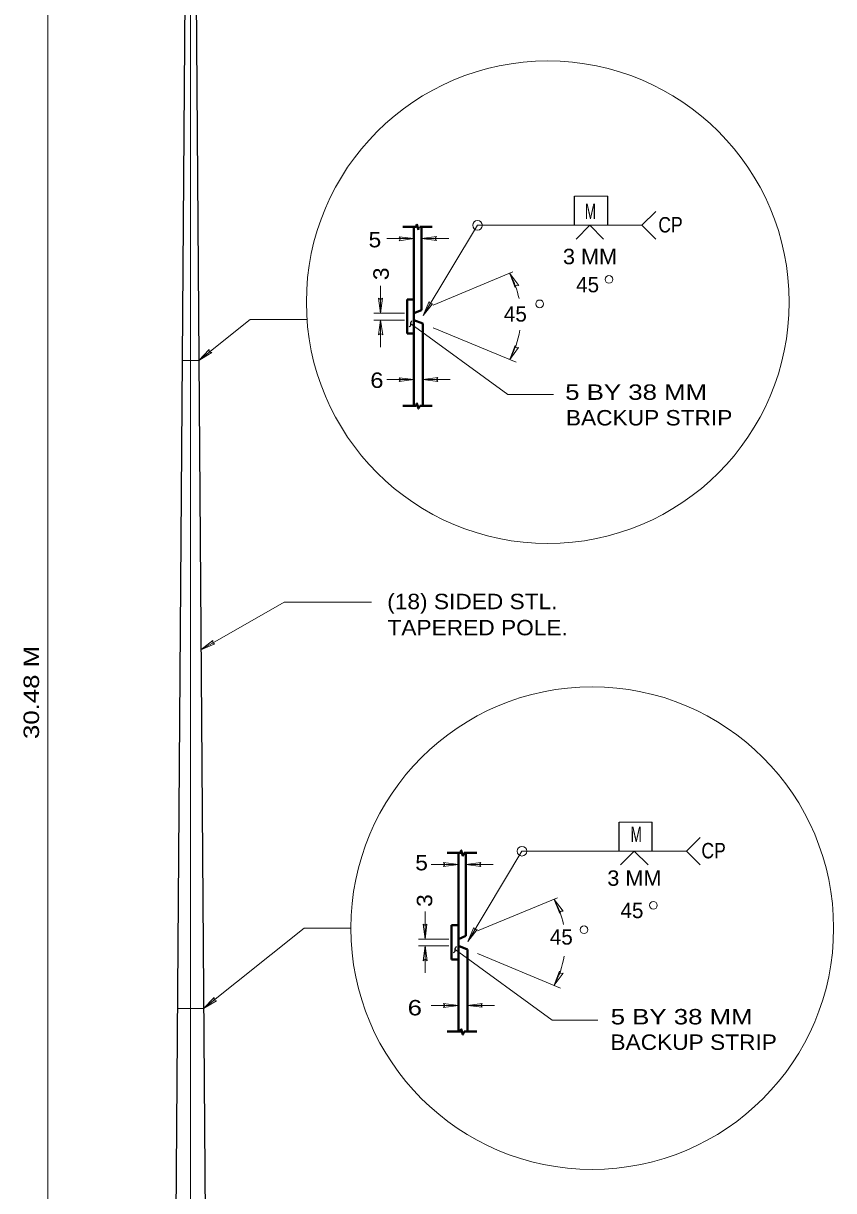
# Model space of a CAD drawing. Extents: x 312583 to 312854, y 144419 to 144597.
# Drawn here: x 312628.1 to 312668, y 144466.1 to 144523.7 of the extents above; entities that cross this region are included whole.
import ezdxf

# ---------------------------------------------------------------- set-up
doc = ezdxf.new("R2010")
doc.units = 0
doc.header["$LTSCALE"] = 0.3
doc.layers.add('1', color=7, linetype='Continuous', lineweight=13)
doc.layers.add('2', color=7, linetype='Continuous', lineweight=13)

msp = doc.modelspace()

# ---------------------------------------------------------------- linework, layer by layer
at = {"layer": '1'}
for p, q in [((312636.3575, 144539.0263), (312636.3575, 144439.0913)), ((312655.2788, 144515.1369), (312656.9118, 144515.1369)), ((312647.5891, 144513.4732), (312647.6504, 144513.6189)), ((312647.3668, 144513.0439), (312646.0251, 144513.0439)), ((312647.7348, 144513.0439), (312649.0764, 144513.0439)), ((312652.2428, 144511.4032), (312648.3098, 144509.7702)), ((312646.9068, 144509.3792), (312645.3888, 144509.3792)), ((312639.2938, 144509.0649), (312636.7714, 144507.0332)), ((312642.0998, 144509.0649), (312639.2938, 144509.0649)), ((312646.9068, 144509.0342), (312645.3888, 144509.0342)), ((312645.7184, 144507.7002), (312645.7184, 144509.0342)), ((312652.3961, 144506.9566), (312648.3098, 144508.6509)), ((312647.3668, 144506.0979), (312646.0251, 144506.0979)), ((312647.8038, 144506.0979), (312649.1531, 144506.0979)), ((312636.8711, 144492.7809), (312640.9651, 144495.1192)), ((312640.9651, 144495.1192), (312645.2661, 144495.1192)), ((312657.4714, 144484.2786), (312659.0968, 144484.2786)), ((312649.5518, 144482.1932), (312648.2101, 144482.1932)), ((312649.9198, 144482.1932), (312651.2614, 144482.1932)), ((312654.4354, 144480.5526), (312650.5024, 144478.9196)), ((312649.0918, 144478.5209), (312647.5814, 144478.5209)), ((312649.0918, 144478.1836), (312647.5814, 144478.1836)), ((312647.9111, 144476.8496), (312647.9111, 144478.1836)), ((312654.5888, 144476.1059), (312650.5024, 144477.8002)), ((312649.5518, 144475.2472), (312648.2101, 144475.2472)), ((312649.9964, 144475.2472), (312651.3381, 144475.2472))]:
    msp.add_line(p, q, dxfattribs=at)
at = {"layer": '1', "lineweight": 25}
for p, q in [((312655.2788, 144513.7032), (312655.2788, 144515.1369)), ((312656.9118, 144513.7032), (312656.9118, 144515.1369)), ((312658.5984, 144513.7032), (312659.2808, 144514.3779)), ((312656.0301, 144513.7032), (312655.3554, 144513.0209)), ((312656.0301, 144513.7032), (312656.7048, 144513.0209)), ((312658.5984, 144513.7032), (312659.2808, 144513.0209)), ((312657.4714, 144482.8526), (312657.4714, 144484.2786)), ((312659.0968, 144482.8526), (312659.0968, 144484.2786)), ((312660.7911, 144482.8526), (312661.4658, 144483.5272)), ((312658.2151, 144482.8526), (312657.5404, 144482.1702)), ((312658.2151, 144482.8526), (312658.8974, 144482.1702)), ((312660.7911, 144482.8526), (312661.4658, 144482.1702))]:
    msp.add_line(p, q, dxfattribs=at)
at = {"layer": '1', "lineweight": 40}
for p, q in [((312647.3668, 144513.6189), (312647.3668, 144509.2106)), ((312648.2638, 144513.6189), (312647.6504, 144513.6189)), ((312647.7348, 144513.6189), (312647.7348, 144509.5249)), ((312647.0294, 144510.0462), (312647.0294, 144508.3672)), ((312647.3668, 144510.0462), (312647.0294, 144510.0462)), ((312647.3668, 144509.3792), (312647.7348, 144509.5249)), ((312647.3668, 144504.8099), (312647.3668, 144509.2106)), ((312647.3668, 144509.0342), (312647.8038, 144508.8579)), ((312647.8038, 144504.8099), (312647.8038, 144508.8579)), ((312647.3668, 144508.3672), (312647.0294, 144508.3672)), ((312648.2638, 144504.8099), (312647.6504, 144504.8099)), ((312649.5518, 144482.7682), (312649.5518, 144478.3599)), ((312650.4564, 144482.7682), (312649.8431, 144482.7682)), ((312649.9198, 144482.7682), (312649.9198, 144478.6742)), ((312649.2144, 144479.1956), (312649.2144, 144477.5166)), ((312649.5518, 144479.1956), (312649.2144, 144479.1956)), ((312649.5518, 144478.5209), (312649.9198, 144478.6742)), ((312649.5518, 144473.9592), (312649.5518, 144478.3599)), ((312649.5518, 144478.1836), (312649.9964, 144477.9996)), ((312649.9964, 144473.9592), (312649.9964, 144477.9996)), ((312649.5518, 144477.5166), (312649.2144, 144477.5166)), ((312650.4564, 144473.9592), (312649.8431, 144473.9592))]:
    msp.add_line(p, q, dxfattribs=at)
for points in [[(312646.8148, 144513.6189), (312647.4664, 144513.6189), (312647.5124, 144513.7416), (312647.5891, 144513.4732)], [(312646.8148, 144504.8099), (312647.4664, 144504.8099), (312647.5124, 144504.9249), (312647.5891, 144504.6642), (312647.6504, 144504.8099)], [(312648.9998, 144482.7682), (312649.6591, 144482.7682), (312649.6974, 144482.8909), (312649.7741, 144482.6226), (312649.8431, 144482.7682)], [(312648.9998, 144473.9592), (312649.6591, 144473.9592), (312649.6974, 144474.0742), (312649.7741, 144473.8136), (312649.8431, 144473.9592)]]:
    msp.add_lwpolyline(points, dxfattribs=at)
at = {"layer": '1'}
for points in [[(312647.8268, 144509.2489), (312650.4948, 144513.7032), (312658.5984, 144513.7032)], [(312646.0634, 144509.3792), (312645.7184, 144509.3792), (312645.7184, 144510.7209)], [(312647.2134, 144508.8502), (312651.9974, 144505.3696), (312654.2361, 144505.3696)], [(312650.0194, 144478.3982), (312652.6874, 144482.8526), (312660.7911, 144482.8526)], [(312648.2484, 144478.5209), (312647.9111, 144478.5209), (312647.9111, 144479.8702)], [(312644.2541, 144479.0576), (312641.9618, 144479.0576), (312637.0014, 144475.0939)], [(312649.3984, 144477.9996), (312654.1824, 144474.5189), (312656.4288, 144474.5189)]]:
    msp.add_lwpolyline(points, dxfattribs=at)
for centre, radius in [((312653.9591, 144509.9109), 11.8926), ((312650.4976, 144513.7016), 0.2381), ((312656.973, 144511.0334), 0.1897), ((312653.5563, 144509.8294), 0.1897), ((312656.148, 144479.06), 11.8926), ((312652.6866, 144482.8506), 0.2381), ((312659.1619, 144480.1824), 0.1897), ((312655.7452, 144478.9784), 0.1897)]:
    msp.add_circle(centre, radius, dxfattribs=at)
for centre, start, end in [((312648.3121, 144509.2089), 11.74697, 29.33835), ((312648.3121, 144509.2089), 330.66165, 350.9999), ((312650.501, 144478.3579), 11.74697, 29.33835), ((312650.501, 144478.3579), 330.66165, 350.9999)]:
    msp.add_arc(centre, 4.3203, start, end, dxfattribs=at)
at = {"layer": '1', "lineweight": 25}
for points in [[(312647.1291, 144508.7046), (312647.1751, 144508.7352), (312647.2058, 144508.7736), (312647.2134, 144508.8272), (312647.2134, 144508.8502), (312647.2134, 144508.8962), (312647.2288, 144508.9346), (312647.2518, 144508.9729), (312647.2671, 144508.9959)], [(312649.3218, 144477.8539), (312649.3678, 144477.8846), (312649.3908, 144477.9229), (312649.3984, 144477.9766), (312649.3984, 144477.9996), (312649.3984, 144478.0456), (312649.4138, 144478.0839), (312649.4368, 144478.1222), (312649.4598, 144478.1452)]]:
    msp.add_spline(points, degree=3, dxfattribs=at)
at = {"layer": '2'}
for p, q in [((312629.3348, 144443.1469), (312629.3348, 144538.9802)), ((312636.7714, 144507.0332), (312635.9434, 144507.0332)), ((312637.0014, 144475.0939), (312635.7058, 144475.0939))]:
    msp.add_line(p, q, dxfattribs=at)
at = {"layer": '2', "lineweight": 25}
for p, q in [((312636.1734, 144538.9802), (312635.4758, 144443.2696)), ((312636.5414, 144538.9802), (312637.2314, 144443.2696))]:
    msp.add_line(p, q, dxfattribs=at)
at = {"layer": '2'}
for points in [[(312646.6308, 144513.1359), (312647.3668, 144513.0439), (312646.6308, 144512.9442), (312646.6998, 144513.0439)], [(312648.4708, 144512.9519), (312647.7348, 144513.0439), (312648.4708, 144513.1512), (312648.3941, 144513.0439)], [(312652.3578, 144510.6366), (312652.0818, 144511.3266), (312652.5264, 144510.7362), (312652.4038, 144510.7439)], [(312645.8104, 144510.1152), (312645.7184, 144509.3792), (312645.6188, 144510.1152), (312645.7184, 144510.0386)], [(312648.2868, 144509.8392), (312647.8268, 144509.2489), (312648.1181, 144509.9389), (312648.1718, 144509.8239)], [(312645.6264, 144508.2982), (312645.7184, 144509.0342), (312645.8258, 144508.2982), (312645.7184, 144508.3749)], [(312652.5188, 144507.6849), (312652.0818, 144507.0946), (312652.3501, 144507.7846), (312652.4038, 144507.6696)], [(312637.4001, 144507.4242), (312636.7714, 144507.0332), (312637.2774, 144507.5776), (312637.2851, 144507.4549)], [(312646.6308, 144506.1899), (312647.3668, 144506.0979), (312646.6308, 144505.9982), (312646.6998, 144506.0979)], [(312648.5398, 144506.0059), (312647.8038, 144506.0979), (312648.5398, 144506.1976), (312648.4708, 144506.0979)], [(312637.5611, 144493.0722), (312636.8711, 144492.7809), (312637.4614, 144493.2409), (312637.4538, 144493.1106)], [(312648.8158, 144482.2852), (312649.5518, 144482.1932), (312648.8158, 144482.0936), (312648.8924, 144482.1932)], [(312650.6558, 144482.1012), (312649.9198, 144482.1932), (312650.6558, 144482.3006), (312650.5868, 144482.1932)], [(312654.5504, 144479.7859), (312654.2668, 144480.4759), (312654.7191, 144479.8856), (312654.5964, 144479.8932)], [(312648.0031, 144479.2569), (312647.9111, 144478.5209), (312647.8114, 144479.2569), (312647.9111, 144479.1879)], [(312650.4718, 144478.9886), (312650.0194, 144478.3982), (312650.3108, 144479.0882), (312650.3568, 144478.9732)], [(312647.8191, 144477.4476), (312647.9111, 144478.1836), (312648.0108, 144477.4476), (312647.9111, 144477.5242)], [(312654.7114, 144476.8342), (312654.2668, 144476.2439), (312654.5351, 144476.9339), (312654.5964, 144476.8189)], [(312637.6378, 144475.4772), (312637.0014, 144475.0939), (312637.5151, 144475.6306), (312637.5228, 144475.5079)], [(312648.8158, 144475.3392), (312649.5518, 144475.2472), (312648.8158, 144475.1476), (312648.8924, 144475.2472)], [(312650.7324, 144475.1552), (312649.9964, 144475.2472), (312650.7324, 144475.3469), (312650.6634, 144475.2472)]]:
    msp.add_lwpolyline(points, close=True, dxfattribs=at)

# ---------------------------------------------------------------- texts
for s, width, p in [('M', 0.65, (312655.7844, 144514.0064)), ('CP', 0.85, (312659.405, 144513.3482)), ('5 ', 1.1, (312645.1299, 144512.6163)), ('3 MM', 1.05, (312654.705, 144511.7841)), ('6 ', 1.15, (312645.2135, 144505.6857)), ('5 BY 38 MM', 1.25, (312654.8169, 144505.0989)), ('BACKUP STRIP', 1.1, (312654.8511, 144503.8362)), ('(18) SIDED STL.', 1.1, (312646.0487, 144494.7796)), ('TAPERED POLE.', 1.1, (312646.0623, 144493.4916)), ('M', 0.65, (312658.0394, 144483.296)), ('CP', 0.85, (312661.5276, 144482.4976)), ('5 ', 1.1, (312647.4309, 144481.906)), ('3 MM', 1.05, (312656.8899, 144481.144)), (' 6 ', 1.25, (312646.7021, 144474.7566)), ('5 BY 38 MM', 1.25, (312657.0578, 144474.3107)), ('BACKUP STRIP', 1.1, (312657.0438, 144473.0557))]:
    msp.add_text(s, height=0.76, dxfattribs=dict(at, width=width)).set_placement(p)
for s, width, p in [('3 ', 1.1, (312646.1233, 144511.0004)), ('30.48 M', 1.25, (312628.8948, 144488.3797)), ('3 ', 1.1, (312648.2665, 144480.1042))]:
    msp.add_text(s, height=0.76, rotation=90, dxfattribs=dict(at, width=width)).set_placement(p)
for p in [(312655.3544, 144510.4), (312651.795, 144508.9552), (312657.5395, 144479.5494), (312654.0578, 144478.2449)]:
    msp.add_text('45', height=0.76, dxfattribs=at).set_placement(p)

doc.saveas('drawing.dxf')
